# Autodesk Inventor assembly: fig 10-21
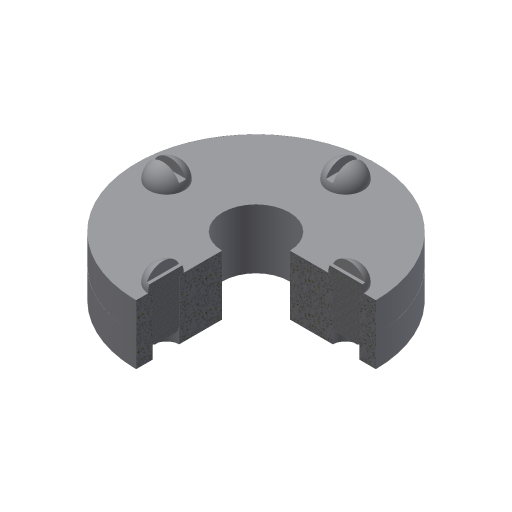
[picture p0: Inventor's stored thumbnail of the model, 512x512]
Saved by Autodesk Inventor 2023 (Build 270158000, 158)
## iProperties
Created: 2002-02
Part Number: fig 10-21
Document SubType Name: Assembly
Designer: ***
Control State: 0
Master: False
Checked Out: False
Shininess: 64.0
Angle Display Precision: 2
Document Length Units: 11269
Document Angle Units: 11279
Document Time Units: 11290
Document Mass Units: 11283
Document Length Units Precision: 3
Document Angle Units Precision: 2
Density: 0.0
Volumn: 0.0
Area: 0.0
PropertySet Name: Model Information
Author: ***
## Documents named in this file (3)
- D:\PROJECTS\Project 2022\Autodesk Inventor For Professional 2023\RESOURCES INVENTOR 2023\RESOURCES INVENTOR 2023\Inventor_2023_Part\Inventor_2023_Part\c10_Inv_2023_prt\fig 10-21.iam
- D:\PROJECTS\Project 2022\Autodesk Inventor For Professional 2023\RESOURCES INVENTOR 2023\RESOURCES INVENTOR 2023\Inventor_2023_Part\Inventor_2023_Part\c10_Inv_2023_prt\Screw.ipt
- D:\PROJECTS\Project 2022\Autodesk Inventor For Professional 2023\RESOURCES INVENTOR 2023\RESOURCES INVENTOR 2023\Inventor_2023_Part\Inventor_2023_Part\c10_Inv_2023_prt\test.ipt
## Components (6 placed, 2 different names)
1. test:1 — Insert:1, Insert:2
2. test:2 — Insert:1
3. Screw:1 — Angle:1, Insert:2
4. Screw:11
5. Screw:12
6. Screw:13
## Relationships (3: Insert 2, Angle 1)
- Insert:1: test:1 ↔ test:2
- Angle:1: Screw:1
- Insert:2: test:1 ↔ Screw:1
